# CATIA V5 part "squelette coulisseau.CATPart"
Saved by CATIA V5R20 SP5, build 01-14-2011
Part number: squelette coulisseau
Publications: "plan coulisseau", "Plan profil cou", "Plancouli"
Bounding box of the stored display mesh (mm): x 0 to 20, y 25.674 to 2799.537, z -86.054 to 1485.26
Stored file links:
  F:\iao fini\squelette coulisseau.CATPart
  F:\iao fini\iao-finipbgliss.CATProduct
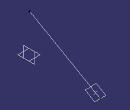
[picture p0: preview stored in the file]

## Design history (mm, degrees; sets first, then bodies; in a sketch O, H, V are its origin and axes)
External parameters (linked from other documents)
  External.angleE = -30 deg
Set1
  Line1: linked copy from another document
  Plane1 "plan dessous": linked copy from another document
  Plane2 "plan profil": linked copy from another document
  Point1: linked copy from another document
Set2
  Line2: type Normal, RefPoint Point1, RefSkin Plane2, Start 0, End 20
  Plane3 "Plancouli": type Angle, RefPlane Plane1, Direction Line2, Angle -30 {= External.angleE}
Body1 (main body)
